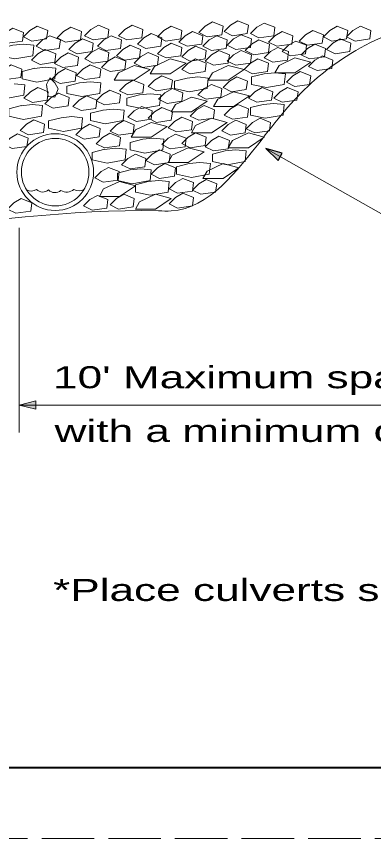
# Model space of a CAD drawing. Extents: x 1083.1 to 1117.1, y 719.4 to 741.4.
# Drawn here: x 1096.63 to 1099.17, y 719.35 to 725.18 of the extents above; entities that cross this region are included whole.
import ezdxf

# ---------------------------------------------------------------- set-up
doc = ezdxf.new("R2010")
doc.units = 0
doc.header["$LTSCALE"] = 0.062
doc.linetypes.add('LONG_DASHED', pattern=[7.5, 6, -1.5])
doc.layers.add('1', color=7, linetype='Continuous', lineweight=13)

msp = doc.modelspace()

# ---------------------------------------------------------------- hatches: boundary and pattern name
at = {"layer": '1'}
for points in [[(1098.51883, 724.20975), (1098.40208, 724.24192), (1098.49, 724.15858)], [(1096.77242, 722.454), (1096.65492, 722.42458), (1096.77242, 722.39517)]]:
    msp.add_hatch(color=256, dxfattribs=at).paths.add_polyline_path(points)

# ---------------------------------------------------------------- linework, layer by layer
for p, q in [((1096.7645, 724.81092), (1096.67467, 724.78842)), ((1096.76258, 724.81042), (1096.83933, 724.81842)), ((1097.08267, 724.70775), (1096.99283, 724.68525)), ((1097.08075, 724.70725), (1097.1575, 724.71525)), ((1096.67042, 724.54642), (1096.58058, 724.52392)), ((1096.6685, 724.54592), (1096.74525, 724.55392)), ((1097.2485, 724.515), (1097.15867, 724.4925)), ((1097.24658, 724.5145), (1097.32333, 724.5225)), ((1096.95275, 724.46117), (1096.86292, 724.43867)), ((1096.95083, 724.46067), (1097.02758, 724.46867)), ((1097.26008, 724.23658), (1097.33683, 724.24458)), ((1097.262, 724.23708), (1097.17217, 724.21458)), ((1096.65492, 723.68042), (1096.65492, 722.22992)), ((1096.65492, 722.42458), (1102.73067, 722.42458)), ((1096.65492, 722.42458), (1096.95417, 722.42458))]:
    msp.add_line(p, q, dxfattribs=at)
at = {"layer": '1', "linetype": 'LONG_DASHED'}
msp.add_lwpolyline([(1083.12642, 719.35408), (1117.12642, 719.35408), (1117.12642, 741.35408), (1083.12642, 741.35408)], close=True, dxfattribs=at)
at = {"layer": '1', "lineweight": 25}
msp.add_lwpolyline([(1116.62642, 719.85408), (1085.12642, 719.85408), (1085.12642, 740.85408)], dxfattribs=at)
at = {"layer": '1', "lineweight": 40}
for points in [[(1116.62642, 719.85408), (1085.12642, 719.85408), (1085.12642, 740.85408), (1116.62642, 740.85408)], [(1116.62642, 719.85408), (1085.12642, 719.85408), (1085.12642, 740.85408)]]:
    msp.add_lwpolyline(points, dxfattribs=at)
at = {"layer": '1'}
for points in [[(1097.21567, 725.1165), (1097.16325, 725.0865), (1097.11833, 725.04158), (1097.17817, 725.01167), (1097.283, 725.02667), (1097.2905, 725.0865)], [(1097.45517, 725.1165), (1097.40275, 725.0865), (1097.35783, 725.04158), (1097.41767, 725.01167), (1097.5225, 725.02667), (1097.53, 725.0865)], [(1098.02408, 725.139), (1097.97167, 725.109), (1097.92675, 725.06408), (1097.98658, 725.03417), (1098.09142, 725.04917), (1098.09892, 725.109)], [(1098.20367, 725.1465), (1098.15125, 725.1165), (1098.10633, 725.07158), (1098.16617, 725.04167), (1098.271, 725.05667), (1098.2785, 725.1165)], [(1098.39083, 725.1315), (1098.33842, 725.1015), (1098.2935, 725.05658), (1098.35333, 725.02667), (1098.45817, 725.04167), (1098.46567, 725.1015)], [(1096.60942, 725.09408), (1096.557, 725.06408), (1096.51208, 725.01917), (1096.57192, 724.98925), (1096.67675, 725.00425), (1096.68425, 725.06408)], [(1096.78158, 725.109), (1096.72917, 725.079), (1096.68425, 725.03408), (1096.74408, 725.00417), (1096.84892, 725.01917), (1096.85642, 725.079)], [(1097.02108, 725.1015), (1096.96867, 725.0715), (1096.92375, 725.02658), (1096.98358, 724.99667), (1097.08842, 725.01167), (1097.09592, 725.0715)], [(1097.58992, 725.05658), (1097.5375, 725.02658), (1097.49258, 724.98167), (1097.55242, 724.95175), (1097.65725, 724.96675), (1097.66475, 725.02658)], [(1097.73217, 725.109), (1097.67975, 725.079), (1097.63483, 725.03408), (1097.69467, 725.00417), (1097.7995, 725.01917), (1097.807, 725.079)], [(1097.88183, 725.07158), (1097.82942, 725.04158), (1097.7845, 724.99667), (1097.84433, 724.96675), (1097.94917, 724.98175), (1097.95667, 725.04158)], [(1098.51817, 725.07158), (1098.46575, 725.04158), (1098.42083, 724.99667), (1098.48067, 724.96675), (1098.5855, 724.98175), (1098.593, 725.04158)], [(1098.73517, 725.07908), (1098.68275, 725.04908), (1098.63783, 725.00417), (1098.69767, 724.97425), (1098.8025, 724.98925), (1098.81, 725.04908)], [(1098.90733, 725.109), (1098.85492, 725.079), (1098.81, 725.03408), (1098.86983, 725.00417), (1098.97467, 725.01917), (1098.98217, 725.079)], [(1099.072, 725.109), (1099.01958, 725.079), (1098.97467, 725.03408), (1099.0345, 725.00417), (1099.13933, 725.01917), (1099.14683, 725.079)], [(1096.87142, 725.04167), (1096.819, 725.01167), (1096.77408, 724.96675), (1096.83392, 724.93683), (1096.93875, 724.95183), (1096.94625, 725.01167)], [(1097.1035, 725.01917), (1097.05108, 724.98917), (1097.00617, 724.94425), (1097.066, 724.91433), (1097.17083, 724.92933), (1097.17833, 724.98917)], [(1097.3055, 725.04167), (1097.25308, 725.01167), (1097.20817, 724.96675), (1097.268, 724.93683), (1097.37283, 724.95183), (1097.38033, 725.01167)], [(1098.05408, 725.04167), (1098.00167, 725.01167), (1097.95675, 724.96675), (1098.01658, 724.93683), (1098.12142, 724.95183), (1098.12892, 725.01167)], [(1098.22625, 725.04908), (1098.17383, 725.01908), (1098.12892, 724.97417), (1098.18875, 724.94425), (1098.29358, 724.95925), (1098.30108, 725.01908)], [(1098.3535, 725.01167), (1098.30108, 724.98167), (1098.25617, 724.93675), (1098.316, 724.90683), (1098.42083, 724.92183), (1098.42833, 724.98167)], [(1098.61542, 725.00417), (1098.563, 724.97417), (1098.51808, 724.92925), (1098.57792, 724.89933), (1098.68275, 724.91433), (1098.69025, 724.97417)], [(1098.92983, 725.01917), (1098.87742, 724.98917), (1098.8325, 724.94425), (1098.89233, 724.91433), (1098.99717, 724.92933), (1099.00467, 724.98917)], [(1096.60933, 724.97425), (1096.5195, 724.95175), (1096.5195, 724.89933), (1096.62433, 724.87692), (1096.75158, 724.89933), (1096.75908, 724.97425), (1096.68417, 724.98175)], [(1096.83958, 724.94317), (1096.78717, 724.91317), (1096.74225, 724.86825), (1096.80208, 724.83833), (1096.90692, 724.85333), (1096.91442, 724.91317)], [(1097.21575, 724.95175), (1097.16333, 724.92175), (1097.11842, 724.87683), (1097.17825, 724.84692), (1097.28308, 724.86192), (1097.29058, 724.92175)], [(1097.44033, 724.97425), (1097.38792, 724.94425), (1097.343, 724.89933), (1097.40283, 724.86942), (1097.50767, 724.88442), (1097.51517, 724.94425)], [(1097.73225, 724.98925), (1097.67983, 724.95925), (1097.63492, 724.91433), (1097.69475, 724.88442), (1097.79958, 724.89942), (1097.80708, 724.95925)], [(1097.90433, 724.96675), (1097.85192, 724.93675), (1097.807, 724.89183), (1097.86683, 724.86192), (1097.97167, 724.87692), (1097.97917, 724.93675)], [(1098.48817, 724.95925), (1098.43575, 724.92925), (1098.39083, 724.88433), (1098.45067, 724.85442), (1098.5555, 724.86942), (1098.563, 724.92925)], [(1098.75017, 724.98175), (1098.69775, 724.95175), (1098.65283, 724.90683), (1098.71267, 724.87692), (1098.8175, 724.89192), (1098.825, 724.95175)], [(1097.00092, 724.92075), (1096.9485, 724.89075), (1096.90358, 724.84583), (1096.96342, 724.81592), (1097.06825, 724.83092), (1097.07575, 724.89075)], [(1097.3355, 724.89192), (1097.28308, 724.86192), (1097.23817, 724.817), (1097.298, 724.78708), (1097.40283, 724.80208), (1097.41033, 724.86192)], [(1097.56758, 724.92183), (1097.51517, 724.89183), (1097.47025, 724.84692), (1097.53008, 724.817), (1097.63492, 724.832), (1097.64242, 724.89183)], [(1098.069, 724.93683), (1098.01658, 724.90683), (1097.97167, 724.86192), (1098.0315, 724.832), (1098.13633, 724.847), (1098.14383, 724.90683)], [(1098.22625, 724.93683), (1098.17383, 724.90683), (1098.12892, 724.86192), (1098.18875, 724.832), (1098.29358, 724.847), (1098.30108, 724.90683)], [(1098.60783, 724.88433), (1098.4955, 724.83192), (1098.46558, 724.7795), (1098.60783, 724.7795), (1098.72008, 724.85442)], [(1098.80258, 724.89933), (1098.75017, 724.86933), (1098.70525, 724.82442), (1098.76508, 724.7945), (1098.86992, 724.8095), (1098.87742, 724.86933)], [(1096.59758, 724.83558), (1096.54517, 724.80558), (1096.50025, 724.76067), (1096.56008, 724.73075), (1096.66492, 724.74575), (1096.67242, 724.80558)], [(1097.15783, 724.83558), (1097.10542, 724.80558), (1097.0605, 724.76067), (1097.12033, 724.73075), (1097.22517, 724.74575), (1097.23267, 724.80558)], [(1097.47017, 724.83192), (1097.35783, 724.7795), (1097.32792, 724.72708), (1097.47017, 724.72708), (1097.58242, 724.802)], [(1097.72458, 724.87683), (1097.61225, 724.82442), (1097.58233, 724.772), (1097.72458, 724.772), (1097.83683, 724.84692)], [(1097.90433, 724.87692), (1097.85192, 724.84692), (1097.807, 724.802), (1097.86683, 724.77208), (1097.97167, 724.78708), (1097.97917, 724.84692)], [(1098.13625, 724.83192), (1098.02392, 724.7795), (1097.994, 724.72708), (1098.13625, 724.72708), (1098.2485, 724.802)], [(1098.346, 724.87692), (1098.29358, 724.84692), (1098.24867, 724.802), (1098.3085, 724.77208), (1098.41333, 724.78708), (1098.42083, 724.84692)], [(1096.983, 724.80867), (1096.93058, 724.77867), (1096.88567, 724.73375), (1096.9455, 724.70383), (1097.05033, 724.71883), (1097.05783, 724.77867)], [(1098.39083, 724.77208), (1098.301, 724.74958), (1098.301, 724.69717), (1098.40583, 724.67475), (1098.53308, 724.69717), (1098.54058, 724.77208), (1098.46567, 724.77958)], [(1098.64542, 724.78708), (1098.593, 724.75708), (1098.54808, 724.71217), (1098.60792, 724.68225), (1098.71275, 724.69725), (1098.72025, 724.75708)], [(1096.93125, 724.66533), (1096.90725, 724.70725), (1096.87133, 724.74325), (1096.84742, 724.69533), (1096.85942, 724.6115), (1096.90725, 724.6055)], [(1097.46275, 724.72717), (1097.41033, 724.69717), (1097.36542, 724.65225), (1097.42525, 724.62233), (1097.53008, 724.63733), (1097.53758, 724.69717)], [(1097.66483, 724.75708), (1097.61242, 724.72708), (1097.5675, 724.68217), (1097.62733, 724.65225), (1097.73217, 724.66725), (1097.73967, 724.72708)], [(1097.84442, 724.74217), (1097.75458, 724.71967), (1097.75458, 724.66725), (1097.85942, 724.64483), (1097.98667, 724.66725), (1097.99417, 724.74217), (1097.91925, 724.74967)], [(1098.19625, 724.74958), (1098.14383, 724.71958), (1098.09892, 724.67467), (1098.15875, 724.64475), (1098.26358, 724.65975), (1098.27108, 724.71958)], [(1096.78583, 724.67417), (1096.73342, 724.64417), (1096.6885, 724.59925), (1096.74833, 724.56933), (1096.85317, 724.58433), (1096.86067, 724.64417)], [(1097.29675, 724.65625), (1097.24433, 724.62625), (1097.19942, 724.58133), (1097.25925, 724.55142), (1097.36408, 724.56642), (1097.37158, 724.62625)], [(1097.73967, 724.66725), (1097.68725, 724.63725), (1097.64233, 724.59233), (1097.70217, 724.56242), (1097.807, 724.57742), (1097.8145, 724.63725)], [(1098.01667, 724.69717), (1097.96425, 724.66717), (1097.91933, 724.62225), (1097.97917, 724.59233), (1098.084, 724.60733), (1098.0915, 724.66717)], [(1098.37592, 724.67475), (1098.3235, 724.64475), (1098.27858, 724.59983), (1098.33842, 724.56992), (1098.44325, 724.58492), (1098.45075, 724.64475)], [(1098.55558, 724.67475), (1098.50317, 724.64475), (1098.45825, 724.59983), (1098.51808, 724.56992), (1098.62292, 724.58492), (1098.63042, 724.64475)], [(1096.93375, 724.63383), (1096.88133, 724.60383), (1096.83642, 724.55892), (1096.89625, 724.529), (1097.00108, 724.544), (1097.00858, 724.60383)], [(1097.13092, 724.61583), (1097.0785, 724.58583), (1097.03358, 724.54092), (1097.09342, 724.511), (1097.19825, 724.526), (1097.20575, 724.58583)], [(1097.50758, 724.62233), (1097.41775, 724.59983), (1097.41775, 724.54742), (1097.52258, 724.525), (1097.64983, 724.54742), (1097.65733, 724.62233), (1097.58242, 724.62983)], [(1097.87433, 724.60733), (1097.762, 724.55492), (1097.73208, 724.5025), (1097.87433, 724.5025), (1097.98658, 724.57742)], [(1098.17375, 724.64475), (1098.06142, 724.59233), (1098.0315, 724.53992), (1098.17375, 724.53992), (1098.286, 724.61483)], [(1097.52258, 724.53992), (1097.47017, 724.50992), (1097.42525, 724.465), (1097.48508, 724.43508), (1097.58992, 724.45008), (1097.59742, 724.50992)], [(1097.66483, 724.53242), (1097.61242, 724.50242), (1097.5675, 724.4575), (1097.62733, 724.42758), (1097.73217, 724.44258), (1097.73967, 724.50242)], [(1097.96425, 724.54742), (1097.91183, 724.51742), (1097.86692, 724.4725), (1097.92675, 724.44258), (1098.03158, 724.45758), (1098.03908, 724.51742)], [(1098.20375, 724.55492), (1098.15133, 724.52492), (1098.10642, 724.48), (1098.16625, 724.45008), (1098.27108, 724.46508), (1098.27858, 724.52492)], [(1098.38325, 724.55492), (1098.29342, 724.53242), (1098.29342, 724.48), (1098.39825, 724.45758), (1098.5255, 724.48), (1098.533, 724.55492), (1098.45808, 724.56242)], [(1096.75892, 724.4455), (1096.7065, 724.4155), (1096.66158, 724.37058), (1096.72142, 724.34067), (1096.82625, 724.35567), (1096.83375, 724.4155)], [(1097.39533, 724.441), (1097.34292, 724.411), (1097.298, 724.36608), (1097.35783, 724.33617), (1097.46267, 724.35117), (1097.47017, 724.411)], [(1097.58992, 724.42767), (1097.47758, 724.37525), (1097.44767, 724.32283), (1097.58992, 724.32283), (1097.70217, 724.39775)], [(1097.807, 724.465), (1097.75458, 724.435), (1097.70967, 724.39008), (1097.7695, 724.36017), (1097.87433, 724.37517), (1097.88183, 724.435)], [(1098.01658, 724.45758), (1097.90425, 724.40517), (1097.87433, 724.35275), (1098.01658, 724.35275), (1098.12883, 724.42767)], [(1098.18883, 724.44258), (1098.13642, 724.41258), (1098.0915, 724.36767), (1098.15133, 724.33775), (1098.25617, 724.35275), (1098.26367, 724.41258)], [(1098.36092, 724.45758), (1098.3085, 724.42758), (1098.26358, 724.38267), (1098.32342, 724.35275), (1098.42825, 724.36775), (1098.43575, 724.42758)], [(1097.15333, 724.41417), (1097.10092, 724.38417), (1097.056, 724.33925), (1097.11583, 724.30933), (1097.22067, 724.32433), (1097.22817, 724.38417)], [(1096.64242, 724.34692), (1096.59, 724.31692), (1096.54508, 724.272), (1096.60492, 724.24208), (1096.70975, 724.25708), (1096.71725, 724.31692)], [(1097.29675, 724.35133), (1097.24433, 724.32133), (1097.19942, 724.27642), (1097.25925, 724.2465), (1097.36408, 724.2615), (1097.37158, 724.32133)], [(1097.53, 724.30775), (1097.44017, 724.28525), (1097.44017, 724.23283), (1097.545, 724.21042), (1097.67225, 724.23283), (1097.67975, 724.30775), (1097.60483, 724.31525)], [(1097.76208, 724.34525), (1097.70967, 724.31525), (1097.66475, 724.27033), (1097.72458, 724.24042), (1097.82942, 724.25542), (1097.83692, 724.31525)], [(1097.90433, 724.35275), (1097.85192, 724.32275), (1097.807, 724.27783), (1097.86683, 724.24792), (1097.97167, 724.26292), (1097.97917, 724.32275)], [(1098.069, 724.33025), (1098.01658, 724.30025), (1097.97167, 724.25533), (1098.0315, 724.22542), (1098.13633, 724.24042), (1098.14383, 724.30025)], [(1098.27858, 724.35275), (1098.16625, 724.30033), (1098.13633, 724.24792), (1098.27858, 724.24792), (1098.39083, 724.32283)], [(1097.85192, 724.24792), (1097.73958, 724.1955), (1097.70967, 724.14308), (1097.85192, 724.14308), (1097.96417, 724.218)], [(1097.47775, 724.20292), (1097.42533, 724.17292), (1097.38042, 724.128), (1097.44025, 724.09808), (1097.54508, 724.11308), (1097.55258, 724.17292)], [(1097.64983, 724.23292), (1097.59742, 724.20292), (1097.5525, 724.158), (1097.61233, 724.12808), (1097.71717, 724.14308), (1097.72467, 724.20292)], [(1098.11383, 724.22542), (1098.024, 724.20292), (1098.024, 724.1505), (1098.12883, 724.12808), (1098.25608, 724.1505), (1098.26358, 724.22542), (1098.18867, 724.23292)], [(1097.68725, 724.13558), (1097.63483, 724.10558), (1097.58992, 724.06067), (1097.64975, 724.03075), (1097.75458, 724.04575), (1097.76208, 724.10558)], [(1097.85933, 724.13558), (1097.7695, 724.11308), (1097.7695, 724.06067), (1097.87433, 724.03825), (1098.00158, 724.06067), (1098.00908, 724.13558), (1097.93417, 724.14308)], [(1098.09892, 724.13558), (1097.98658, 724.08317), (1097.95667, 724.03075), (1098.09892, 724.03075), (1098.21117, 724.10567)], [(1097.28775, 724.10925), (1097.23533, 724.07925), (1097.19042, 724.03433), (1097.25025, 724.00442), (1097.35508, 724.01942), (1097.36258, 724.07925)], [(1097.44017, 724.09067), (1097.35033, 724.06817), (1097.35033, 724.01575), (1097.45517, 723.99333), (1097.58242, 724.01575), (1097.58992, 724.09067), (1097.515, 724.09817)], [(1097.36533, 724.00825), (1097.253, 723.95583), (1097.22308, 723.90342), (1097.36533, 723.90342), (1097.47758, 723.97833)], [(1097.56742, 724.00833), (1097.47758, 723.98583), (1097.47758, 723.93342), (1097.58242, 723.911), (1097.70967, 723.93342), (1097.71717, 724.00833), (1097.64225, 724.01583)], [(1097.8145, 724.03075), (1097.76208, 724.00075), (1097.71717, 723.95583), (1097.777, 723.92592), (1097.88183, 723.94092), (1097.88933, 724.00075)], [(1097.97917, 724.02325), (1097.92675, 723.99325), (1097.88183, 723.94833), (1097.94167, 723.91842), (1098.0465, 723.93342), (1098.054, 723.99325)], [(1097.20825, 723.91092), (1097.15583, 723.88092), (1097.11092, 723.836), (1097.17075, 723.80608), (1097.27558, 723.82108), (1097.28308, 723.88092)], [(1097.39533, 723.91842), (1097.34292, 723.88842), (1097.298, 723.8435), (1097.35783, 723.81358), (1097.46267, 723.82858), (1097.47017, 723.88842)], [(1097.61983, 723.91842), (1097.5075, 723.866), (1097.47758, 723.81358), (1097.61983, 723.81358), (1097.73208, 723.8885)], [(1097.8145, 723.92592), (1097.76208, 723.89592), (1097.71717, 723.851), (1097.777, 723.82108), (1097.88183, 723.83608), (1097.88933, 723.89592)], [(1096.66925, 723.8885), (1096.61683, 723.8585), (1096.57192, 723.81358), (1096.63175, 723.78367), (1096.73658, 723.79867), (1096.74408, 723.8585)], [(1096.77242, 722.454), (1096.65492, 722.42458), (1096.77242, 722.39517)]]:
    msp.add_lwpolyline(points, close=True, dxfattribs=at)
for points in [[(1096.67467, 724.78842), (1096.67467, 724.736), (1096.7795, 724.71358), (1096.90675, 724.736), (1096.91425, 724.81092), (1096.83933, 724.81842)], [(1096.99283, 724.68525), (1096.99283, 724.63283), (1097.09767, 724.61042), (1097.22492, 724.63283), (1097.23242, 724.70775), (1097.1575, 724.71525)], [(1096.45508, 724.67183), (1096.45508, 724.61942), (1096.55992, 724.597), (1096.68717, 724.61942), (1096.69467, 724.69433), (1096.61975, 724.70183)], [(1096.58058, 724.52392), (1096.58058, 724.4715), (1096.68542, 724.44908), (1096.81267, 724.4715), (1096.82017, 724.54642), (1096.74525, 724.55392)], [(1097.15867, 724.4925), (1097.15867, 724.44008), (1097.2635, 724.41767), (1097.39075, 724.44008), (1097.39825, 724.515), (1097.32333, 724.5225)], [(1096.86292, 724.43867), (1096.86292, 724.38625), (1096.96775, 724.36383), (1097.095, 724.38625), (1097.1025, 724.46117), (1097.02758, 724.46867)], [(1097.17217, 724.21458), (1097.17217, 724.16217), (1097.277, 724.13975), (1097.40425, 724.16217), (1097.41175, 724.23708), (1097.33683, 724.24458)], [(1098.40208, 724.24192), (1099.36308, 723.69958), (1099.56025, 723.69958)]]:
    msp.add_lwpolyline(points, dxfattribs=at)
at = {"layer": '1', "lineweight": 25}
msp.add_lwpolyline([(1098.51883, 724.20975), (1098.40208, 724.24192), (1098.49, 724.15858)], close=True, dxfattribs=at)
at = {"layer": '1'}
for radius in [0.27205, 0.23917]:
    msp.add_circle((1096.90983, 724.07542), radius, dxfattribs=at)
for centre, radius, start, end in [((1096.73867, 724.01003), 0.06863, 242.09271, 303.99685), ((1096.82211, 723.9977), 0.06339, 224.68758, 310.32369), ((1096.90819, 723.99395), 0.06339, 224.68758, 310.32369), ((1096.99117, 724.00959), 0.0765, 236.73157, 312.43249), ((1097.07888, 724.00446), 0.06275, 234.89581, 305.8904)]:
    msp.add_arc(centre, radius, start, end, dxfattribs=at)
msp.add_spline([(1087.80692, 725.11858), (1089.39375, 725.11858), (1089.96258, 725.463), (1090.33683, 725.1485), (1091.66917, 725.10358), (1092.268, 724.99875), (1092.77692, 724.63933), (1093.19608, 724.14517), (1093.89967, 723.77075), (1097.64217, 723.80075), (1097.732, 723.80075), (1098.37575, 724.30992), (1098.75, 724.72925), (1099.28892, 725.05867), (1101.53442, 725.10358), (1102.01342, 725.1485), (1102.56733, 725.59783), (1103.04642, 725.1635), (1104.0045, 725.13358)], degree=3, dxfattribs=at)

# ---------------------------------------------------------------- texts
at = {"layer": '1', "width": 1.5}
for s, p in [("10' Maximum spacing between culverts*", (1096.8945, 722.54442)), ('with a minimum of one culvert', (1096.90517, 722.16408)), ('*Place culverts so as not to back up water.', (1096.8945, 721.03725))]:
    msp.add_text(s, height=0.156, dxfattribs=at).set_placement(p)

doc.saveas('drawing.dxf')
